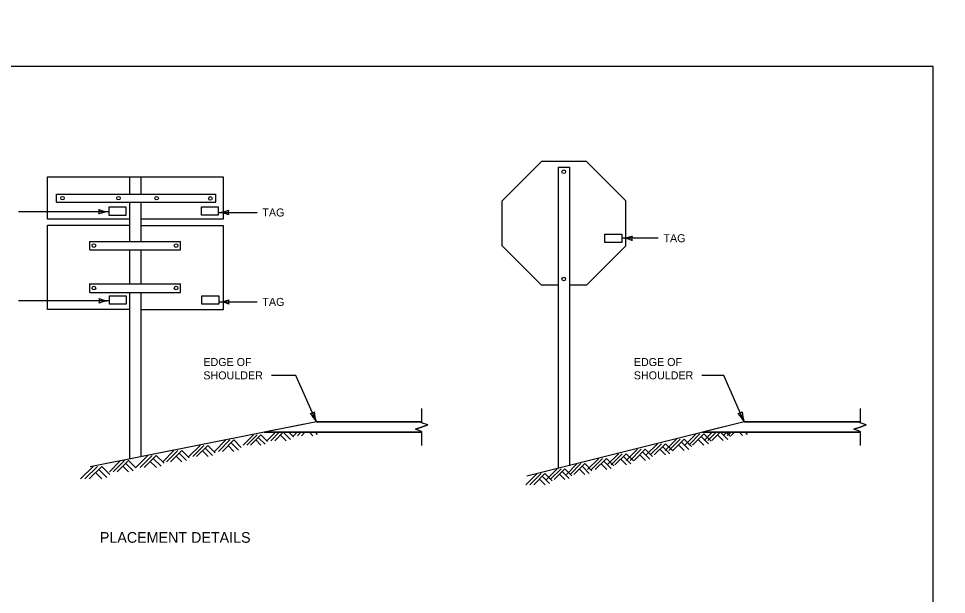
# Model space of a CAD drawing. Extents: x 49991.4 to 50021, y 49987.6 to 50011.4.
# Drawn here: x 50014.08 to 50021.04, y 50004.2 to 50008.52 of the extents above; entities that cross this region are included whole.
import ezdxf

# ---------------------------------------------------------------- set-up
doc = ezdxf.new("R2010")
doc.units = 0
for name, color, linetype in [('Level 1', 7, 'Continuous'), ('Level 2', 7, 'Continuous'), ('Level 3', 7, 'Continuous'), ('Level 6', 7, 'Continuous')]:
    doc.layers.add(name, color=color, linetype=linetype)

msp = doc.modelspace()

# ---------------------------------------------------------------- linework, layer by layer
at = {"layer": 'Level 1'}
for p, q in [((50021.0378, 50008.5236), (50021.0378, 50008.5236)), ((50018.0031, 50007.4513), (50017.7078, 50007.156)), ((50018.3406, 50007.4513), (50018.0031, 50007.4513)), ((50018.3406, 50007.4513), (50018.636, 50007.156)), ((50018.1296, 50005.1507), (50018.1296, 50007.4097)), ((50018.1296, 50007.4097), (50018.214, 50007.4097)), ((50018.214, 50007.4097), (50018.214, 50005.1717)), ((50014.3002, 50007.0185), (50014.3002, 50007.3363)), ((50014.3002, 50007.3363), (50015.0012, 50007.3363)), ((50014.9169, 50007.2076), (50014.9169, 50007.3363)), ((50015.0012, 50007.3363), (50015.6172, 50007.3363)), ((50015.0012, 50007.3363), (50015.0012, 50007.2076)), ((50015.6172, 50007.3363), (50015.6172, 50007.0199)), ((50014.3685, 50007.2076), (50015.5618, 50007.2076)), ((50014.3685, 50007.1454), (50014.3685, 50007.2076)), ((50015.5618, 50007.1454), (50015.5618, 50007.2076)), ((50014.3685, 50007.1454), (50015.5618, 50007.1454)), ((50014.7621, 50007.0471), (50014.7621, 50007.1104)), ((50014.7621, 50007.1104), (50014.8886, 50007.1104)), ((50014.8886, 50007.1104), (50014.8886, 50007.0471)), ((50014.9169, 50006.852), (50014.9169, 50007.1454)), ((50015.0012, 50007.1454), (50015.0012, 50006.9727)), ((50015.4537, 50007.0489), (50015.4537, 50007.1121)), ((50015.4537, 50007.1121), (50015.5802, 50007.1121)), ((50015.5802, 50007.1121), (50015.5802, 50007.0489)), ((50017.7078, 50006.8185), (50017.7078, 50007.156)), ((50017.7078, 50006.8185), (50017.7078, 50007.156)), ((50018.636, 50006.8185), (50018.636, 50007.156)), ((50014.8886, 50007.0471), (50014.7621, 50007.0471)), ((50015.5802, 50007.0489), (50015.4537, 50007.0489)), ((50014.9169, 50007.0185), (50014.3002, 50007.0185)), ((50014.3011, 50006.3418), (50014.3011, 50006.9748)), ((50014.3011, 50006.9748), (50014.9169, 50006.9748)), ((50015.6172, 50007.0199), (50015.0012, 50007.0199)), ((50015.0012, 50006.9727), (50015.6172, 50006.9727)), ((50015.0012, 50006.9727), (50015.0012, 50006.852)), ((50015.6172, 50006.9727), (50015.6172, 50006.3398)), ((50018.4787, 50006.8444), (50018.4787, 50006.9078)), ((50018.4787, 50006.9078), (50018.6052, 50006.9078)), ((50018.6052, 50006.9078), (50018.6052, 50006.8444)), ((50014.6191, 50006.7879), (50014.6191, 50006.8539)), ((50014.6191, 50006.852), (50015.2976, 50006.852)), ((50015.2976, 50006.7879), (50015.2976, 50006.852)), ((50017.7078, 50006.8185), (50018.0031, 50006.5231)), ((50018.636, 50006.8185), (50018.3406, 50006.5231)), ((50018.6052, 50006.8444), (50018.4787, 50006.8444)), ((50014.6191, 50006.7879), (50015.2976, 50006.7879)), ((50014.9169, 50006.6887), (50014.9169, 50006.7879)), ((50015.0012, 50006.7879), (50015.0012, 50006.6285)), ((50014.9169, 50006.5337), (50014.9169, 50006.6887)), ((50015.0012, 50006.6285), (50015.0012, 50006.5337)), ((50014.6191, 50006.4695), (50014.6191, 50006.5356)), ((50014.6191, 50006.5337), (50015.2976, 50006.5337)), ((50014.6191, 50006.4695), (50015.2976, 50006.4695)), ((50014.9169, 50006.3425), (50014.9169, 50006.4695)), ((50015.0012, 50006.4695), (50015.0012, 50005.237)), ((50015.2976, 50006.4695), (50015.2976, 50006.5337)), ((50018.1296, 50006.5231), (50018.0031, 50006.5231)), ((50018.3406, 50006.5231), (50018.214, 50006.5231)), ((50014.7648, 50006.3804), (50014.7648, 50006.4438)), ((50014.7648, 50006.4438), (50014.8912, 50006.4438)), ((50014.8912, 50006.4438), (50014.8912, 50006.3804)), ((50015.4574, 50006.3809), (50015.4574, 50006.4443)), ((50015.4574, 50006.4443), (50015.5839, 50006.4443)), ((50015.5839, 50006.4443), (50015.5839, 50006.3809)), ((50014.9169, 50006.3418), (50014.3011, 50006.3418)), ((50014.8912, 50006.3804), (50014.7648, 50006.3804)), ((50014.9169, 50005.2202), (50014.9169, 50006.3425)), ((50015.6172, 50006.3398), (50015.0012, 50006.3398)), ((50015.5839, 50006.3809), (50015.4574, 50006.3809)), ((50016.3158, 50005.4987), (50014.6215, 50005.1614)), ((50016.3158, 50005.4987), (50015.924, 50005.4207)), ((50016.3158, 50005.4987), (50017.1044, 50005.4987)), ((50017.1044, 50005.4987), (50016.3158, 50005.4987)), ((50017.1044, 50005.4921), (50017.1044, 50005.4987)), ((50017.1501, 50005.4759), (50017.1044, 50005.4921)), ((50019.5223, 50005.4987), (50017.8941, 50005.0918)), ((50019.5223, 50005.4987), (50019.2102, 50005.4207)), ((50019.5223, 50005.4987), (50020.3906, 50005.4987)), ((50020.3906, 50005.4987), (50019.5223, 50005.4987)), ((50020.3906, 50005.4921), (50020.3906, 50005.4987)), ((50020.4363, 50005.4759), (50020.3906, 50005.4921)), ((50017.0587, 50005.4435), (50017.1044, 50005.4597)), ((50017.1044, 50005.4273), (50017.0587, 50005.4435)), ((50017.1044, 50005.4597), (50017.1501, 50005.4759)), ((50017.1044, 50005.4207), (50017.1044, 50005.4273)), ((50020.3449, 50005.4435), (50020.3906, 50005.4597)), ((50020.3906, 50005.4273), (50020.3449, 50005.4435)), ((50020.3906, 50005.4597), (50020.4363, 50005.4759)), ((50020.3906, 50005.4207), (50020.3906, 50005.4273)), ((50015.5514, 50005.2775), (50015.6372, 50005.3632)), ((50015.5815, 50005.2775), (50015.6671, 50005.3632)), ((50015.6115, 50005.2775), (50015.6971, 50005.3632)), ((50015.6971, 50005.3632), (50015.753, 50005.3076)), ((50015.7668, 50005.3242), (50015.845, 50005.4024)), ((50015.7942, 50005.3242), (50015.8724, 50005.4024)), ((50015.8217, 50005.3242), (50015.8998, 50005.4024)), ((50015.8611, 50005.3637), (50015.9006, 50005.3242)), ((50015.8806, 50005.3829), (50015.9313, 50005.3322)), ((50015.8998, 50005.4024), (50015.9506, 50005.3516)), ((50017.1044, 50005.4207), (50015.924, 50005.4207)), ((50015.924, 50005.4207), (50017.1044, 50005.4207)), ((50015.9452, 50005.3576), (50016.0085, 50005.4209)), ((50015.9747, 50005.3576), (50016.0381, 50005.4209)), ((50016.0043, 50005.3576), (50016.0676, 50005.4209)), ((50016.047, 50005.4001), (50016.0895, 50005.3576)), ((50016.0681, 50005.4209), (50016.1227, 50005.366)), ((50016.1097, 50005.4209), (50016.1435, 50005.387)), ((50016.1453, 50005.3954), (50016.1707, 50005.4209)), ((50016.1747, 50005.3954), (50016.2002, 50005.4209)), ((50016.2042, 50005.3954), (50016.2297, 50005.4209)), ((50016.2639, 50005.4209), (50016.2895, 50005.3954)), ((50016.3057, 50005.4209), (50016.3227, 50005.4038)), ((50018.9289, 50005.2841), (50019.0135, 50005.3684)), ((50018.9585, 50005.2841), (50019.0429, 50005.3684)), ((50018.9881, 50005.2841), (50019.0724, 50005.3684)), ((50019.0724, 50005.3684), (50019.1272, 50005.3135)), ((50019.0765, 50005.3251), (50019.1609, 50005.4095)), ((50019.1059, 50005.3251), (50019.1904, 50005.4095)), ((50019.1355, 50005.3251), (50019.2198, 50005.4095)), ((50019.1782, 50005.3676), (50019.2208, 50005.3251)), ((50019.1992, 50005.3886), (50019.254, 50005.3338)), ((50020.3906, 50005.4207), (50019.2102, 50005.4207)), ((50019.2102, 50005.4207), (50019.4194, 50005.4207)), ((50019.2198, 50005.4095), (50019.2748, 50005.3546)), ((50019.2209, 50005.3592), (50019.2824, 50005.4207)), ((50019.2505, 50005.3592), (50019.3119, 50005.4207)), ((50019.2799, 50005.3592), (50019.3415, 50005.4207)), ((50019.3227, 50005.4018), (50019.3653, 50005.3592)), ((50019.3456, 50005.4207), (50019.3985, 50005.3678)), ((50019.3677, 50005.3986), (50019.3456, 50005.4207)), ((50019.3456, 50005.4207), (50020.3906, 50005.4207)), ((50019.3659, 50005.3968), (50019.3898, 50005.4207)), ((50019.3886, 50005.4195), (50019.3677, 50005.3986)), ((50019.3873, 50005.4207), (50019.4193, 50005.3887)), ((50019.4034, 50005.4047), (50019.3886, 50005.4195)), ((50019.3955, 50005.3968), (50019.4194, 50005.4207)), ((50019.4194, 50005.4207), (50019.4034, 50005.4047)), ((50019.425, 50005.3968), (50019.449, 50005.4207)), ((50019.4863, 50005.4207), (50019.5103, 50005.3968)), ((50019.5282, 50005.4207), (50019.5435, 50005.4054)), ((50015.1642, 50005.2003), (50015.2485, 50005.2847)), ((50015.1937, 50005.2003), (50015.2781, 50005.2847)), ((50015.2233, 50005.2003), (50015.3076, 50005.2847)), ((50015.3076, 50005.2847), (50015.3625, 50005.2297)), ((50015.3594, 50005.2382), (50015.4439, 50005.3226)), ((50015.389, 50005.2382), (50015.4733, 50005.3226)), ((50015.4185, 50005.2382), (50015.5029, 50005.3226)), ((50015.4821, 50005.3017), (50015.5371, 50005.2469)), ((50015.5029, 50005.3226), (50015.5577, 50005.2678)), ((50015.6548, 50005.3208), (50015.6981, 50005.2775)), ((50015.6762, 50005.342), (50015.7318, 50005.2863)), ((50018.6371, 50005.2098), (50018.7214, 50005.2942)), ((50018.6666, 50005.2098), (50018.751, 50005.2942)), ((50018.6962, 50005.2098), (50018.7805, 50005.2942)), ((50018.7805, 50005.2942), (50018.8353, 50005.2393)), ((50018.7877, 50005.251), (50018.8721, 50005.3354)), ((50018.8173, 50005.251), (50018.9017, 50005.3354)), ((50018.8467, 50005.251), (50018.9312, 50005.3354)), ((50018.8895, 50005.2935), (50018.932, 50005.251)), ((50018.9104, 50005.3144), (50018.9652, 50005.2596)), ((50018.9312, 50005.3354), (50018.986, 50005.2806)), ((50019.0307, 50005.3266), (50019.0732, 50005.2841)), ((50019.0516, 50005.3475), (50019.1066, 50005.2925)), ((50014.9625, 50005.1575), (50015.0525, 50005.2474)), ((50014.9941, 50005.1575), (50015.084, 50005.2474)), ((50015.0255, 50005.1575), (50015.1155, 50005.2474)), ((50015.0934, 50005.2252), (50015.1518, 50005.1667)), ((50015.1155, 50005.2474), (50015.174, 50005.189)), ((50015.266, 50005.2428), (50015.3085, 50005.2003)), ((50015.2869, 50005.2637), (50015.3417, 50005.2088)), ((50015.4612, 50005.2807), (50015.5037, 50005.2382)), ((50018.3472, 50005.1407), (50018.4317, 50005.2252)), ((50018.3768, 50005.1407), (50018.4611, 50005.2252)), ((50018.4063, 50005.1407), (50018.4907, 50005.2252)), ((50018.4907, 50005.2252), (50018.5455, 50005.1702)), ((50018.4945, 50005.1761), (50018.5788, 50005.2604)), ((50018.5239, 50005.1761), (50018.6085, 50005.2604)), ((50018.5535, 50005.1761), (50018.6379, 50005.2604)), ((50018.5963, 50005.2186), (50018.6388, 50005.1761)), ((50018.6172, 50005.2395), (50018.672, 50005.1845)), ((50018.6379, 50005.2604), (50018.6928, 50005.2055)), ((50018.7389, 50005.2523), (50018.7813, 50005.2098)), ((50018.7597, 50005.2733), (50018.8147, 50005.2185)), ((50014.5487, 50005.0717), (50014.6423, 50005.1652)), ((50014.5815, 50005.0717), (50014.675, 50005.1652)), ((50014.6142, 50005.0717), (50014.7078, 50005.1652)), ((50014.7078, 50005.1652), (50014.7686, 50005.1044)), ((50014.7643, 50005.1241), (50014.8486, 50005.2085)), ((50014.7937, 50005.1241), (50014.8781, 50005.2085)), ((50014.8233, 50005.1241), (50014.9077, 50005.2085)), ((50014.8659, 50005.1667), (50014.9085, 50005.1241)), ((50014.8869, 50005.1876), (50014.9418, 50005.1327)), ((50014.9077, 50005.2085), (50014.9625, 50005.1535)), ((50015.0711, 50005.2028), (50015.1164, 50005.1575)), ((50018.0404, 50005.0665), (50018.1213, 50005.1475)), ((50018.0686, 50005.0665), (50018.1497, 50005.1475)), ((50018.097, 50005.0665), (50018.1779, 50005.1475)), ((50018.1779, 50005.1475), (50018.2305, 50005.095)), ((50018.1892, 50005.1043), (50018.2704, 50005.1857)), ((50018.2177, 50005.1043), (50018.2989, 50005.1857)), ((50018.2461, 50005.1043), (50018.3274, 50005.1857)), ((50018.2871, 50005.1453), (50018.3281, 50005.1043)), ((50018.3073, 50005.1655), (50018.3602, 50005.1127)), ((50018.3274, 50005.1857), (50018.3801, 50005.1329)), ((50018.449, 50005.1832), (50018.4915, 50005.1407)), ((50018.4699, 50005.2043), (50018.5248, 50005.1493)), ((50014.6616, 50005.1187), (50014.7087, 50005.0717)), ((50014.6848, 50005.142), (50014.7455, 50005.0812)), ((50017.8855, 50005.0271), (50017.9699, 50005.1115)), ((50017.9151, 50005.0271), (50017.9994, 50005.1115)), ((50017.9445, 50005.0271), (50018.029, 50005.1115)), ((50018.0082, 50005.0906), (50018.0631, 50005.0358)), ((50018.029, 50005.1115), (50018.0838, 50005.0567)), ((50018.138, 50005.1073), (50018.1787, 50005.0665)), ((50018.158, 50005.1274), (50018.2106, 50005.0748)), ((50017.9873, 50005.0697), (50018.0298, 50005.0271))]:
    msp.add_line(p, q, dxfattribs=at)
msp.add_lwpolyline([(50020.9378, 50008.1646), (50009.7374, 50008.1646), (50009.7374, 49999.8856), (50020.9378, 49999.8856)], close=True, dxfattribs=at)
for centre in [(50018.1698, 50007.3744), (50014.4133, 50007.1766), (50014.833, 50007.1766), (50015.1187, 50007.1766), (50015.521, 50007.1745), (50014.6483, 50006.8208), (50015.2645, 50006.8208), (50018.1698, 50006.5706), (50014.6483, 50006.5025), (50015.2645, 50006.5025)]:
    msp.add_circle(centre, 0.0135, dxfattribs=at)
at = {"layer": 'Level 3'}
for p, q in [((50014.7621, 50007.0749), (50014.0843, 50007.0749)), ((50015.5802, 50007.0691), (50015.8712, 50007.0691)), ((50018.8771, 50006.8761), (50018.6052, 50006.8761)), ((50014.7648, 50006.4069), (50014.0843, 50006.4069)), ((50015.5839, 50006.3984), (50015.8712, 50006.3984)), ((50016.1619, 50005.8477), (50015.9792, 50005.8477)), ((50016.3158, 50005.4987), (50016.1619, 50005.8477)), ((50019.3683, 50005.8477), (50019.2052, 50005.8477)), ((50019.5223, 50005.4987), (50019.3683, 50005.8477))]:
    msp.add_line(p, q, dxfattribs=at)
for centre, radius, start, end in [((50014.7713, 50007.297), 0.2223, 247.45601, 267.63952), ((50014.6339, 50007.0749), 0.0548, 342.13882, 17.86118), ((50014.7736, 50006.8422), 0.233, 92.82731, 112.07716), ((50015.5687, 50007.3018), 0.233, 272.82731, 292.07716), ((50015.571, 50006.847), 0.2223, 67.45601, 87.63952), ((50015.7084, 50007.0691), 0.0548, 162.13882, 197.86118), ((50018.594, 50007.1088), 0.233, 272.74992, 291.99977), ((50018.7334, 50006.8759), 0.0548, 162.06143, 197.78379), ((50018.5957, 50006.654), 0.2223, 67.37862, 87.56213), ((50014.774, 50006.629), 0.2223, 247.45601, 267.63952), ((50014.6366, 50006.4069), 0.0548, 342.13882, 17.86118), ((50014.7763, 50006.1742), 0.233, 92.82731, 112.07716), ((50015.5724, 50006.6311), 0.233, 272.82731, 292.07716), ((50015.5747, 50006.1763), 0.2223, 67.45601, 87.63952), ((50015.7121, 50006.3984), 0.0548, 162.13882, 197.86118), ((50016.2641, 50005.616), 0.0548, 275.94273, 311.66509), ((50016.1075, 50005.3943), 0.233, 26.63122, 45.88107), ((50016.5227, 50005.58), 0.2223, 181.25992, 201.44343), ((50019.4706, 50005.616), 0.0548, 275.94273, 311.66509), ((50019.314, 50005.3943), 0.233, 26.63122, 45.88107), ((50019.7292, 50005.58), 0.2223, 181.25992, 201.44343)]:
    msp.add_arc(centre, radius, start, end, dxfattribs=at)
at = {"layer": 'Level 6'}
for p, q in [((50017.1044, 50005.5987), (50017.1044, 50005.4921)), ((50020.3906, 50005.5987), (50020.3906, 50005.4921)), ((50017.1501, 50005.4759), (50017.1044, 50005.4921)), ((50020.4363, 50005.4759), (50020.3906, 50005.4921)), ((50017.1044, 50005.4597), (50017.0587, 50005.4435)), ((50017.1044, 50005.4273), (50017.0587, 50005.4435)), ((50017.1501, 50005.4759), (50017.1044, 50005.4597)), ((50017.1044, 50005.4273), (50017.1044, 50005.3207)), ((50020.3906, 50005.4597), (50020.3449, 50005.4435)), ((50020.3906, 50005.4273), (50020.3449, 50005.4435)), ((50020.4363, 50005.4759), (50020.3906, 50005.4597)), ((50020.3906, 50005.4273), (50020.3906, 50005.3207))]:
    msp.add_line(p, q, dxfattribs=at)

# ---------------------------------------------------------------- texts
at = {"layer": 'Level 2'}
for s, height, p in [('TAG', 0.06, (50015.9112, 50007.0391)), ('TAG', 0.06, (50018.9171, 50006.8461)), ('TAG', 0.06, (50015.9112, 50006.3684)), ('EDGE OF', 0.06, (50015.4689, 50005.9177)), ('EDGE OF', 0.06, (50018.6949, 50005.9177)), ('SHOULDER', 0.06, (50015.4689, 50005.8177)), ('SHOULDER', 0.06, (50018.6949, 50005.8177)), ('PLACEMENT DETAILS', 0.08, (50014.693, 50004.5922))]:
    msp.add_text(s, height=height, dxfattribs=at).set_placement(p)

doc.saveas('drawing.dxf')
